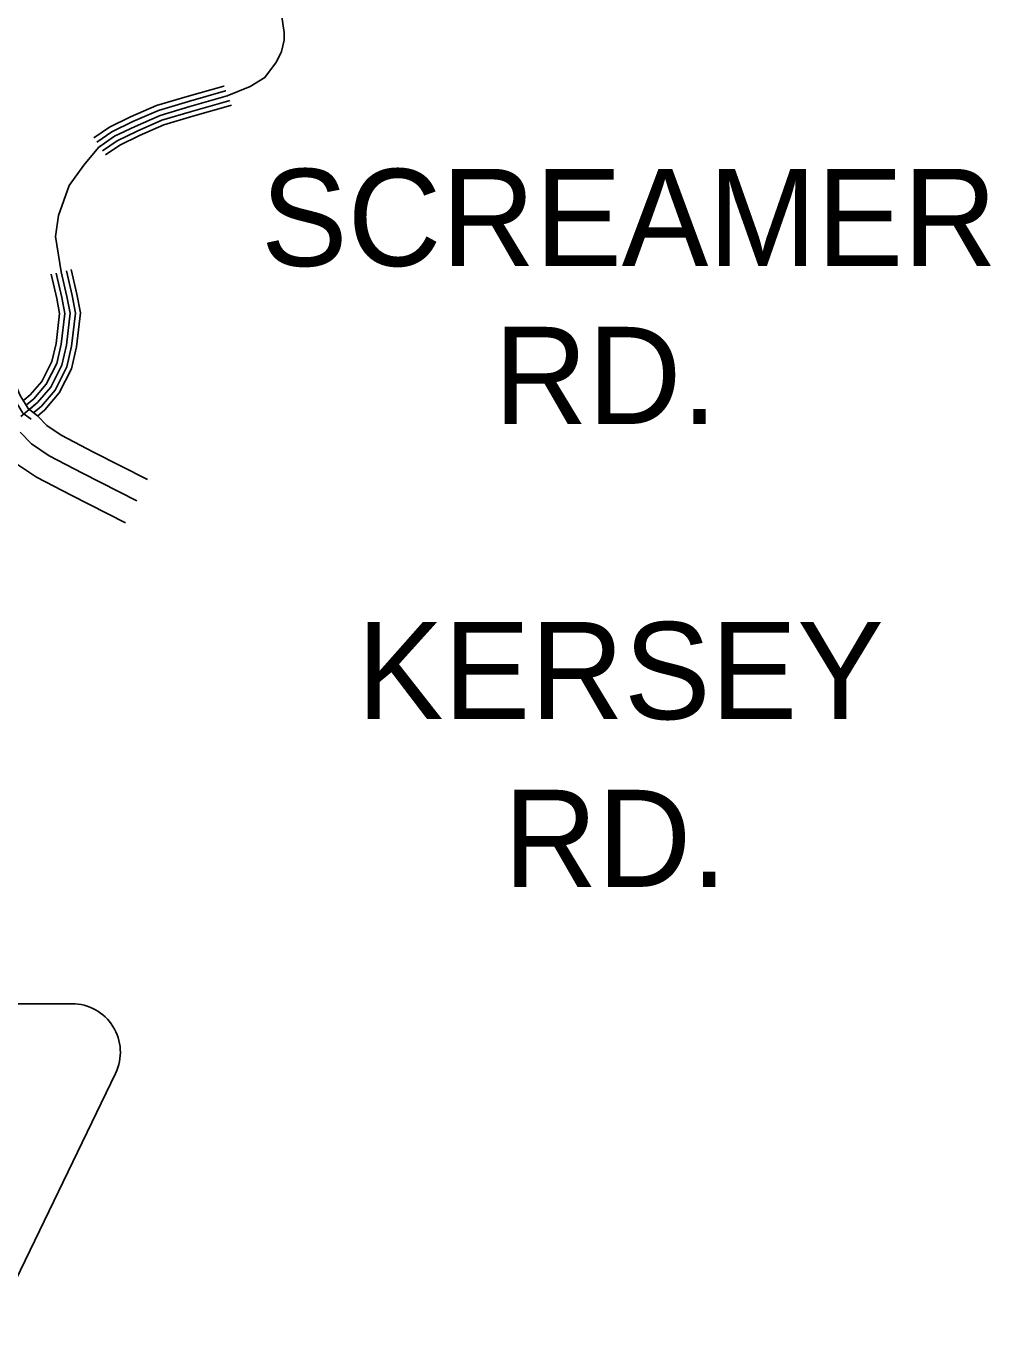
# Model space of a CAD drawing. Extents: x 1551132 to 1791609, y 378168 to 563823.
# Drawn here: x 1624306 to 1627982, y 401324 to 406291 of the extents above; entities that cross this region are included whole.
import ezdxf

# ---------------------------------------------------------------- set-up
doc = ezdxf.new("R2010")
doc.units = 0
for name, color, linetype in [('DESIGN - ROW - Easement Linework and Patterning', 7, 'Continuous'), ('DESIGN - ROW - Right-of-Way and Easement Labels', 7, 'Continuous'), ('SURVEY - DRAINAGE - Natural Features', 7, 'Continuous'), ('SURVEY - PROPERTY - Owners', 7, 'Continuous'), ('SURVEY - TRANSPORTATION - Roads', 7, 'Continuous')]:
    doc.layers.add(name, color=color, linetype=linetype)

msp = doc.modelspace()

# ---------------------------------------------------------------- linework, layer by layer
at = {"layer": 'DESIGN - ROW - Easement Linework and Patterning'}
for p, q in [((1624480.835, 402566.485), (1623376.461, 402566.462)), ((1624647.168, 402301.21), (1624174.132, 401323.595))]:
    msp.add_line(p, q, dxfattribs=at)
msp.add_arc((1624480.825, 402381.681), 184.803, 334.179933, 90.001225, dxfattribs=at)
at = {"layer": 'SURVEY - DRAINAGE - Natural Features'}
for points in [[(1625271.835, 406387.09), (1625289.768, 406267.087), (1625289.76, 406237.087), (1625279.785, 406195.085), (1625259.836, 406155.093), (1625215.962, 406095.108), (1625160.121, 406061.123), (1625072.365, 406025.156), (1624930.777, 405985.196), (1624817.104, 405951.237), (1624721.373, 405909.261), (1624643.6, 405871.293), (1624581.776, 405829.309), (1624525.928, 405761.324), (1624470.079, 405683.346), (1624430.18, 405569.36), (1624418.205, 405489.358), (1624440.129, 405355.354), (1624462.054, 405261.344), (1624474.012, 405197.342), (1624460.037, 405075.347), (1624442.079, 404999.353), (1624400.188, 404915.368), (1624350.323, 404857.383), (1624286.508, 404803.398)], [(1625059.407, 406063.082), (1625059.299, 406063.032), (1624919.619, 406023.614), (1624803.296, 405988.863), (1624704.565, 405945.57), (1624623.492, 405905.986), (1624564.252, 405865.76)], [(1625067.007, 406044.573), (1625065.832, 406044.09), (1624925.202, 406004.405), (1624810.204, 405970.046), (1624712.965, 405927.411), (1624633.542, 405888.644), (1624575.493, 405849.209)], [(1625074.598, 406026.072), (1625072.365, 406025.156), (1624930.777, 405985.196), (1624817.104, 405951.237), (1624721.373, 405909.261), (1624643.6, 405871.293), (1624586.726, 405832.667)], [(1625082.19, 406007.572), (1625078.898, 406006.222), (1624936.351, 405965.987), (1624824.004, 405932.428), (1624729.781, 405891.11), (1624653.658, 405853.943), (1624597.959, 405816.125)], [(1625089.406, 405989.997), (1625085.106, 405988.23), (1624941.651, 405947.745), (1624830.571, 405914.553), (1624737.764, 405873.86), (1624663.208, 405837.467), (1624608.634, 405800.4)], [(1624401.33, 405345.604), (1624422.896, 405253.127), (1624433.588, 405195.917), (1624420.563, 405082.247), (1624404.222, 405013.062), (1624366.614, 404937.677), (1624322.065, 404885.875), (1624298.016, 404865.525)], [(1624420.813, 405350.146), (1624442.479, 405257.235), (1624453.796, 405196.625), (1624440.304, 405078.797), (1624423.146, 405006.212), (1624383.405, 404926.518), (1624336.198, 404871.625), (1624308.282, 404848.016)], [(1624440.288, 405354.688), (1624462.054, 405261.344), (1624474.012, 405197.342), (1624460.037, 405075.347), (1624442.079, 404999.353), (1624400.188, 404915.368), (1624350.323, 404857.383), (1624320.357, 404832.032)], [(1624459.762, 405359.23), (1624481.628, 405265.452), (1624494.228, 405198.059), (1624479.77, 405071.897), (1624461.012, 404992.495), (1624416.971, 404904.218), (1624364.447, 404843.141), (1624336.206, 404819.249)], [(1624478.27, 405363.546), (1624500.228, 405269.361), (1624513.428, 405198.734), (1624498.519, 405068.622), (1624478.995, 404985.986), (1624432.921, 404893.617), (1624377.872, 404829.607), (1624349.598, 404805.682)]]:
    msp.add_lwpolyline(points, dxfattribs=at)
at = {"layer": 'SURVEY - PROPERTY - Owners'}
for points in [[(1624350.739, 404804.898), (1624385.38, 404769.097), (1624440.562, 404732.113), (1624562.826, 404668.495), (1624768.988, 404563.242)], [(1624163.869, 404730.171), (1624173.244, 404714.887), (1624218.617, 404675.395), (1624266.083, 404626.343), (1624346.073, 404572.725), (1624478.07, 404504.04), (1624684.873, 404398.463)], [(1624283.566, 404743.872), (1624326.89, 404699.104), (1624394.23, 404653.961), (1624521.269, 404587.859), (1624727.747, 404482.448)]]:
    msp.add_lwpolyline(points, dxfattribs=at)
at = {"layer": 'SURVEY - TRANSPORTATION - Roads'}
for points in [[(1624177.594, 405109.489), (1624188.735, 405082.139), (1624242.059, 404915.259), (1624260.383, 404871.717), (1624293.916, 404817.057), (1624325.49, 404793.756)], [(1624201.41, 405119.198), (1624212.926, 405090.922), (1624266.208, 404924.176), (1624283.324, 404883.5), (1624313.774, 404833.874), (1624349.389, 404805.99)]]:
    msp.add_lwpolyline(points, dxfattribs=at)

# ---------------------------------------------------------------- texts
at = {"layer": 'DESIGN - ROW - Right-of-Way and Easement Labels'}
for s, p in [('SCREAMER', (1625201.12, 405377.147)), ('RD.', (1626088.557, 404775.465)), ('KERSEY', (1625566.935, 403650.644)), ('RD.', (1626125.88, 403011.627))]:
    msp.add_text(s, height=369.9913, rotation=0.000033, dxfattribs=at).set_placement(p)

doc.saveas('drawing.dxf')
